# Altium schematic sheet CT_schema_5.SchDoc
size 297 x 173 mm
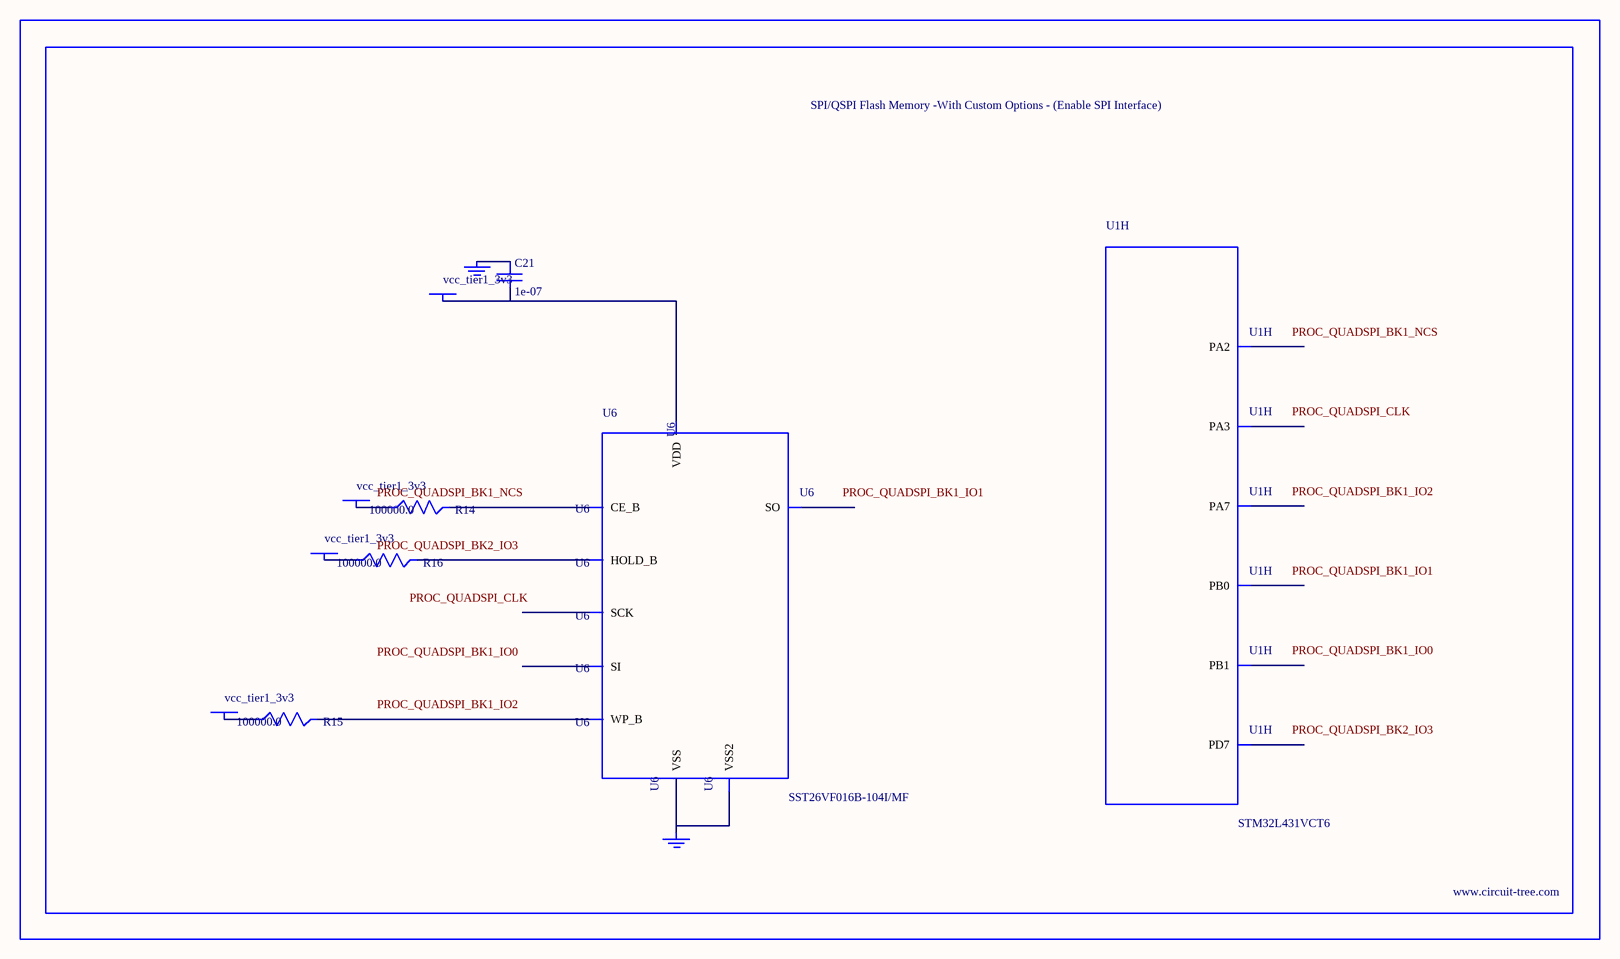
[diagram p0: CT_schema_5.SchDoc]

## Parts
BORDER4  (no value)
C21  1e-07  [C0402]
GND_INSTANCE_4_0  (no value)
GND_INSTANCE_4_1  (no value)
POWER_INSTANCE_4_0  vcc_tier1_3v3
POWER_INSTANCE_4_1  vcc_tier1_3v3
POWER_INSTANCE_4_2  vcc_tier1_3v3
POWER_INSTANCE_4_3  vcc_tier1_3v3
R14  100000.0  [R0603]
R15  100000.0  [R0603]
R16  100000.0  [R0603]
U1  STM32L431VCT6  [LQFP100]  (part H of 8)
U6  SST26VF016B-104I/MF  [WFDN-8]

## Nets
NetC21_1: C21.1 GND_INSTANCE_4_0.0(GND)
NetC21_2: C21.2 POWER_INSTANCE_4_3.0(PWR) U6.8(VDD)
NetGND_INSTANCE_4_1_0: GND_INSTANCE_4_1.0(GND) U6.4(VSS) U6.9(VSS2)
NetPOWER_INSTANCE_4_0_0: POWER_INSTANCE_4_0.0(PWR) R14.1
NetPOWER_INSTANCE_4_1_0: POWER_INSTANCE_4_1.0(PWR) R15.1
NetPOWER_INSTANCE_4_2_0: POWER_INSTANCE_4_2.0(PWR) R16.1
NetR14_2: R14.2 U6.1(CE_B)
NetR15_2: R15.2 U6.3(WP_B)
NetR16_2: R16.2 U6.7(HOLD_B)

Not connected (* = marked no-connect by the designer): U1 25(PA2) 26(PA3) 32(PA7) 35(PB0) 36(PB1) 88(PD7); U6 2(SO) 5(SI) 6(SCK)

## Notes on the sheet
- Labels drawn without touching a wire or pin: PROC_QUADSPI_BK1_IO0, PROC_QUADSPI_BK1_IO1, PROC_QUADSPI_BK1_IO2, PROC_QUADSPI_BK1_NCS, PROC_QUADSPI_BK2_IO3, PROC_QUADSPI_CLK

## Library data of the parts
BORDER4 = BORDER_PAGE4
C21 = C0402C104K3RACTU
GND_INSTANCE_4_0 GND_INSTANCE_4_1 = GND
POWER_INSTANCE_4_0-POWER_INSTANCE_4_3 = PWR
R14-R16 = RC0603JR-07100KL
